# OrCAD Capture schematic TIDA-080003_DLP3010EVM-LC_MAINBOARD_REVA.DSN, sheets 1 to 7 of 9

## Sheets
1 P09: Disclaimer
2 P03: IT6801: size D
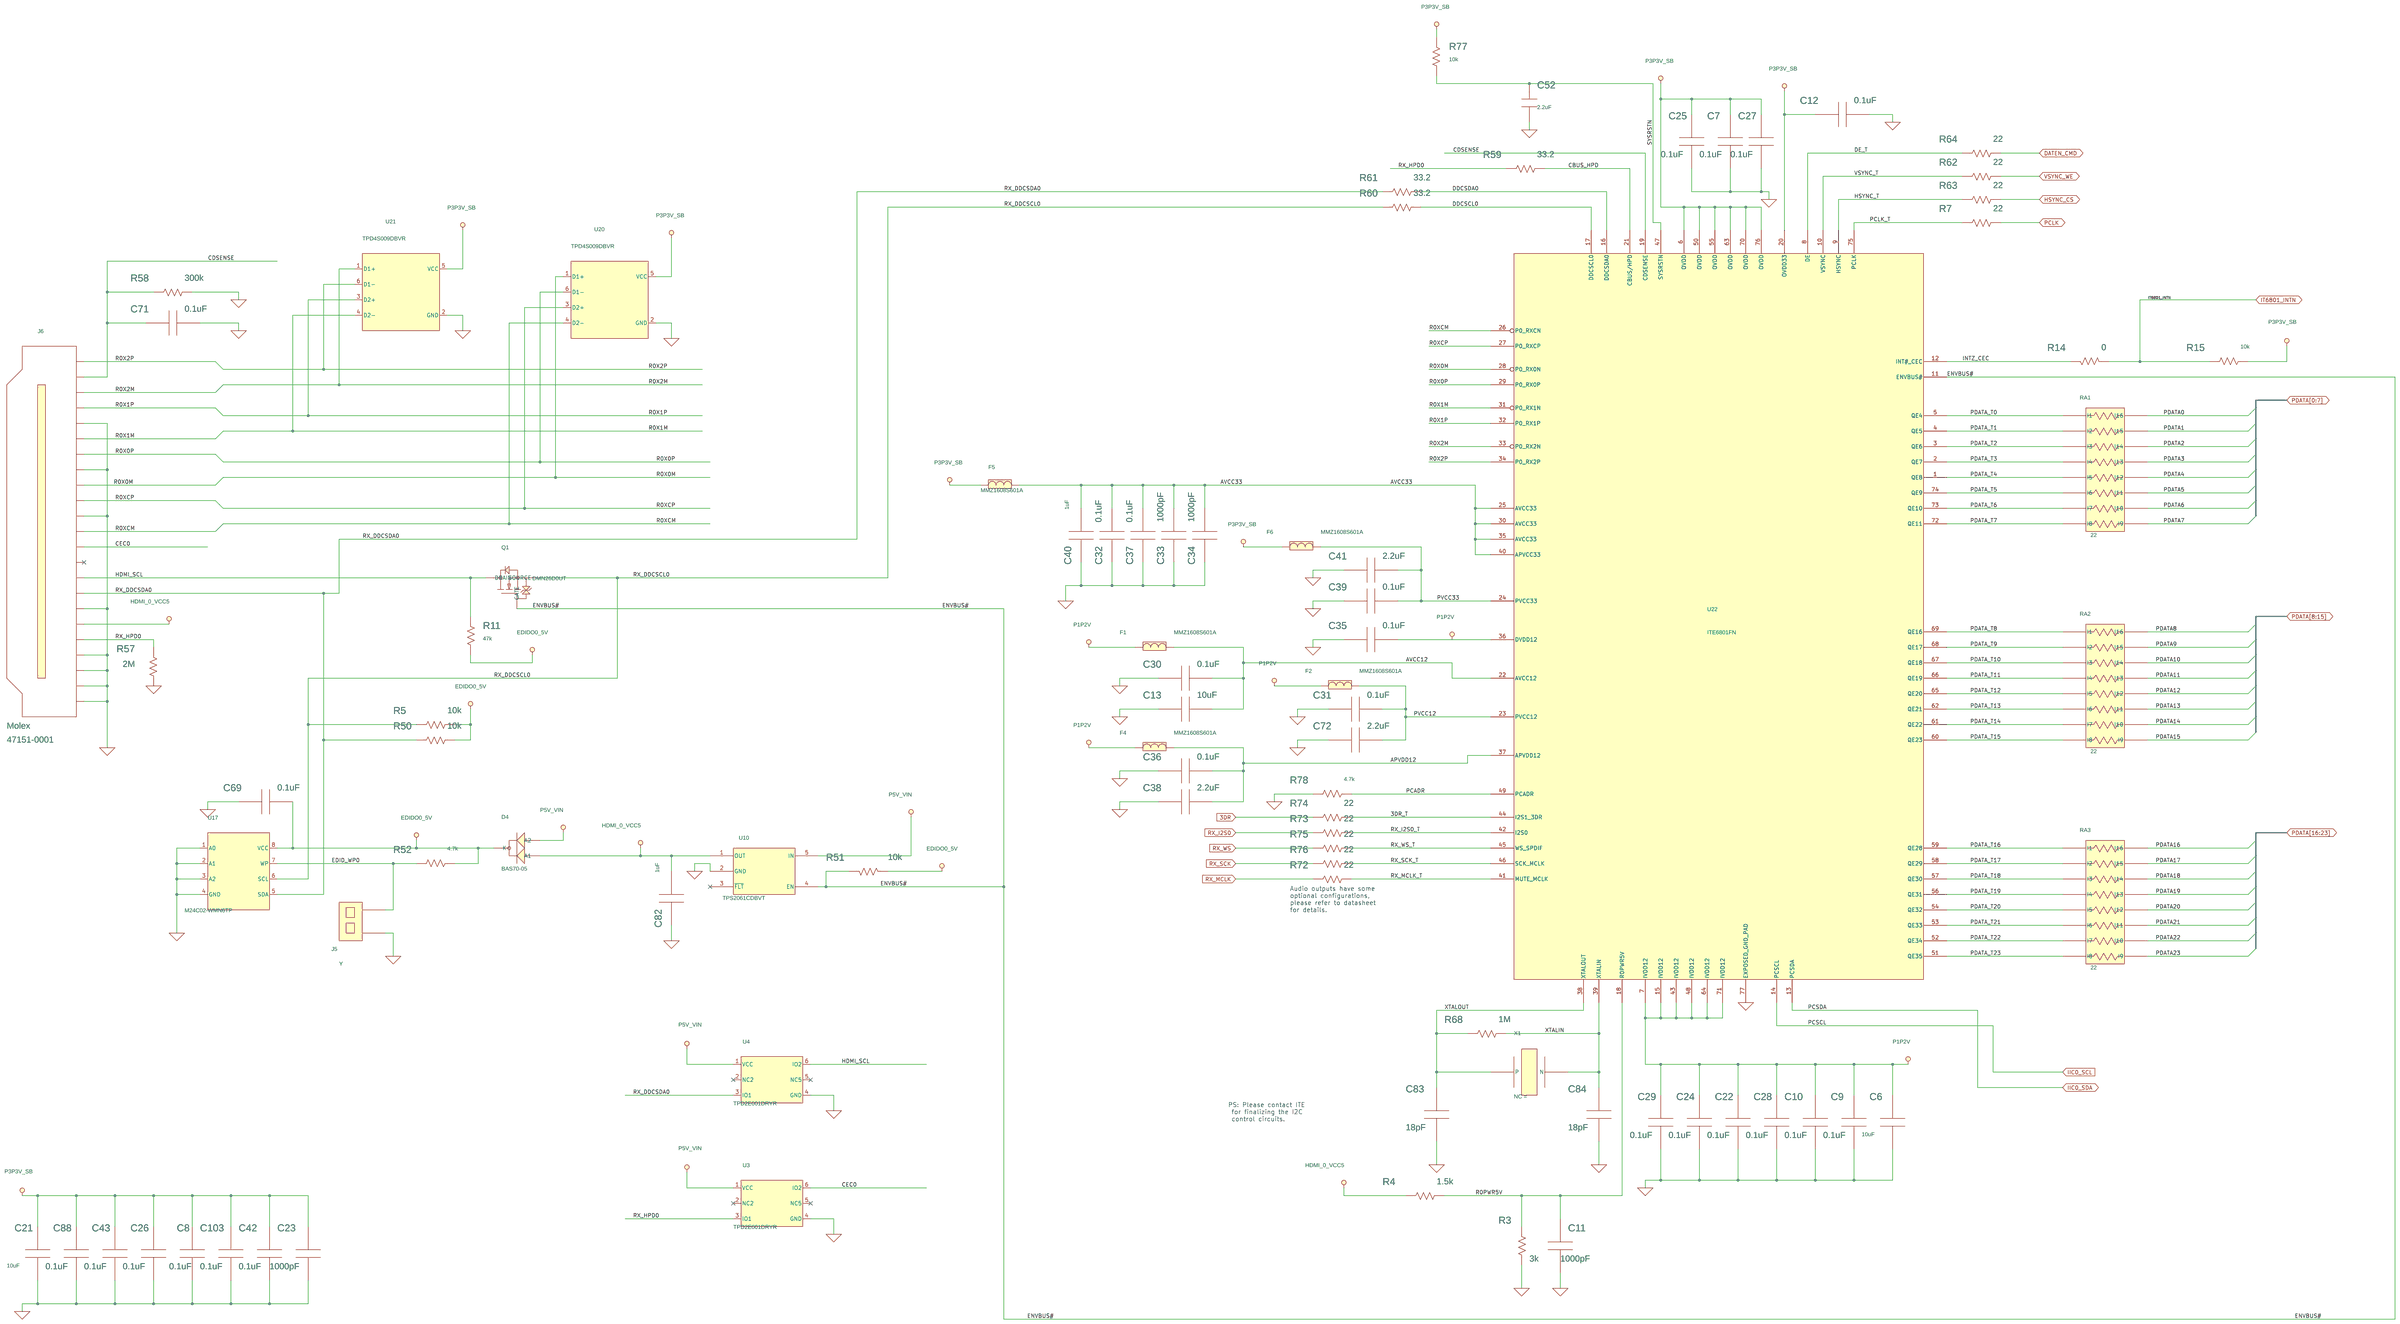
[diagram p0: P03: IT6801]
3 P01: Title: title: TIDA-080003 DLP® 3010 Light Control Main Board; rev: A; company: Texas Instruments Inc.
4 P08: Revisions
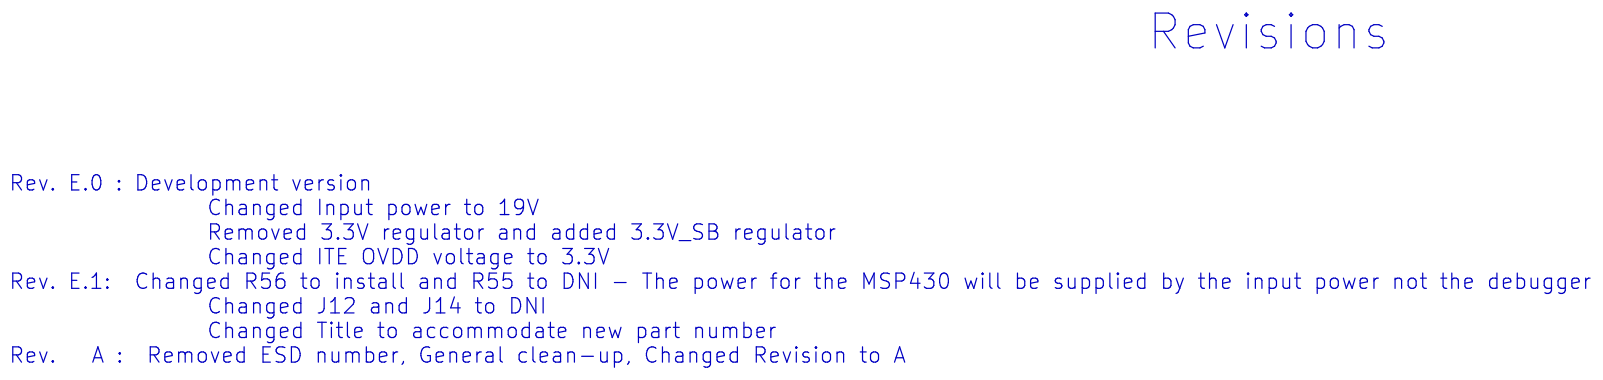
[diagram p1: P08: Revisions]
5 P02: DLP CONNECTION: size D
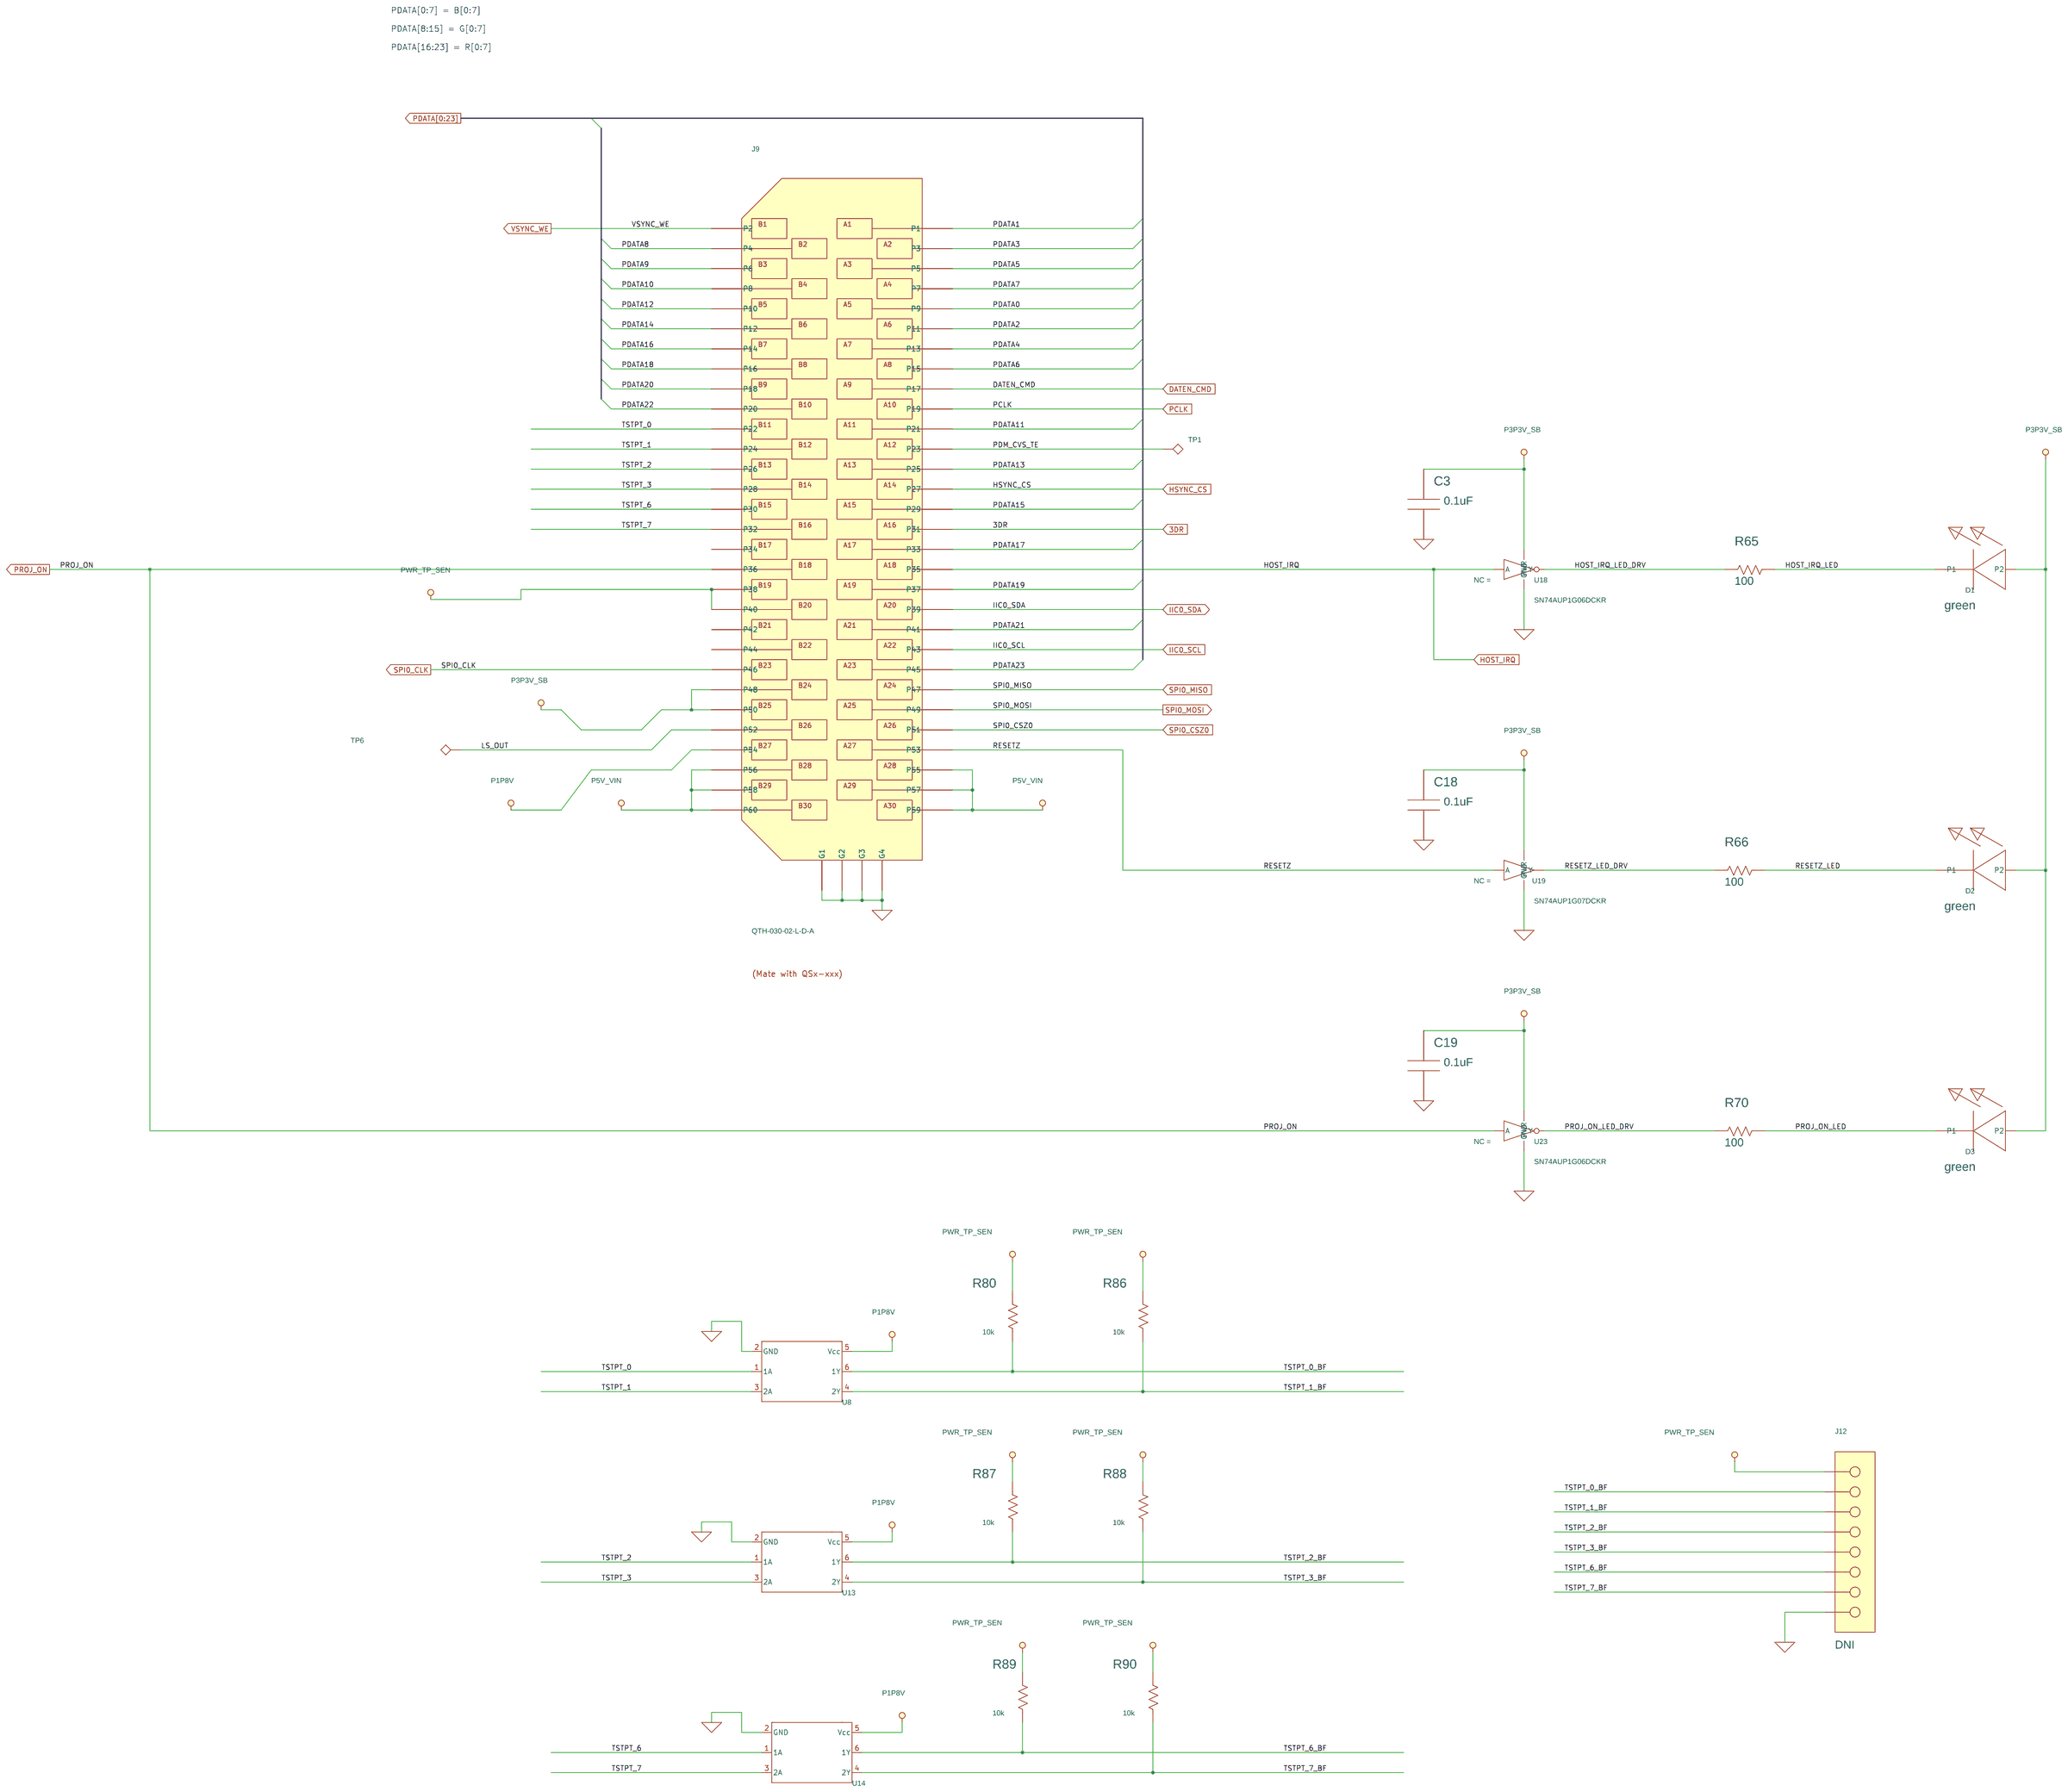
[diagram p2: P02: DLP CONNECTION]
6 P05: Audio Output: size D
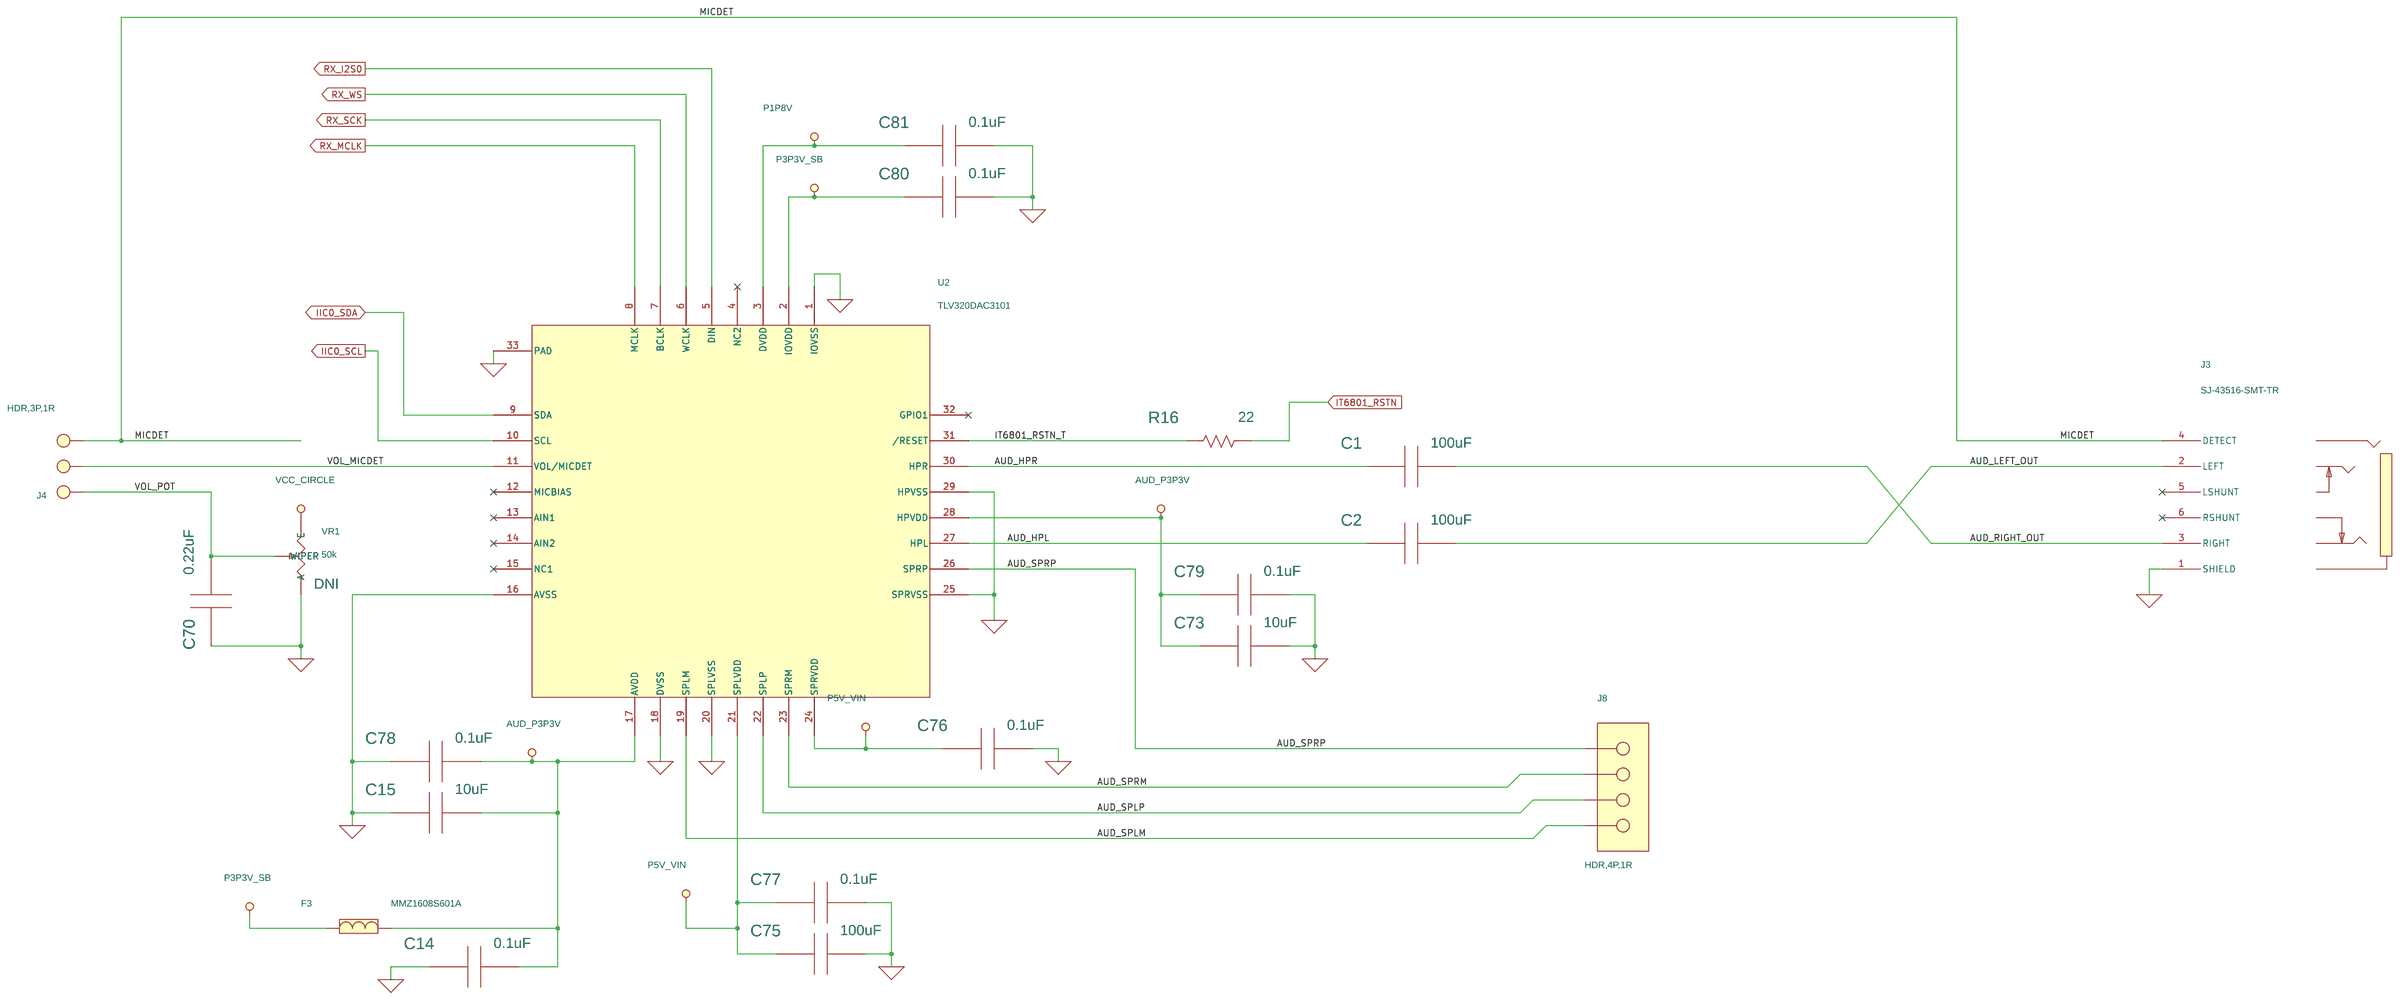
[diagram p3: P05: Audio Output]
7 P06: I2C Connections: size D
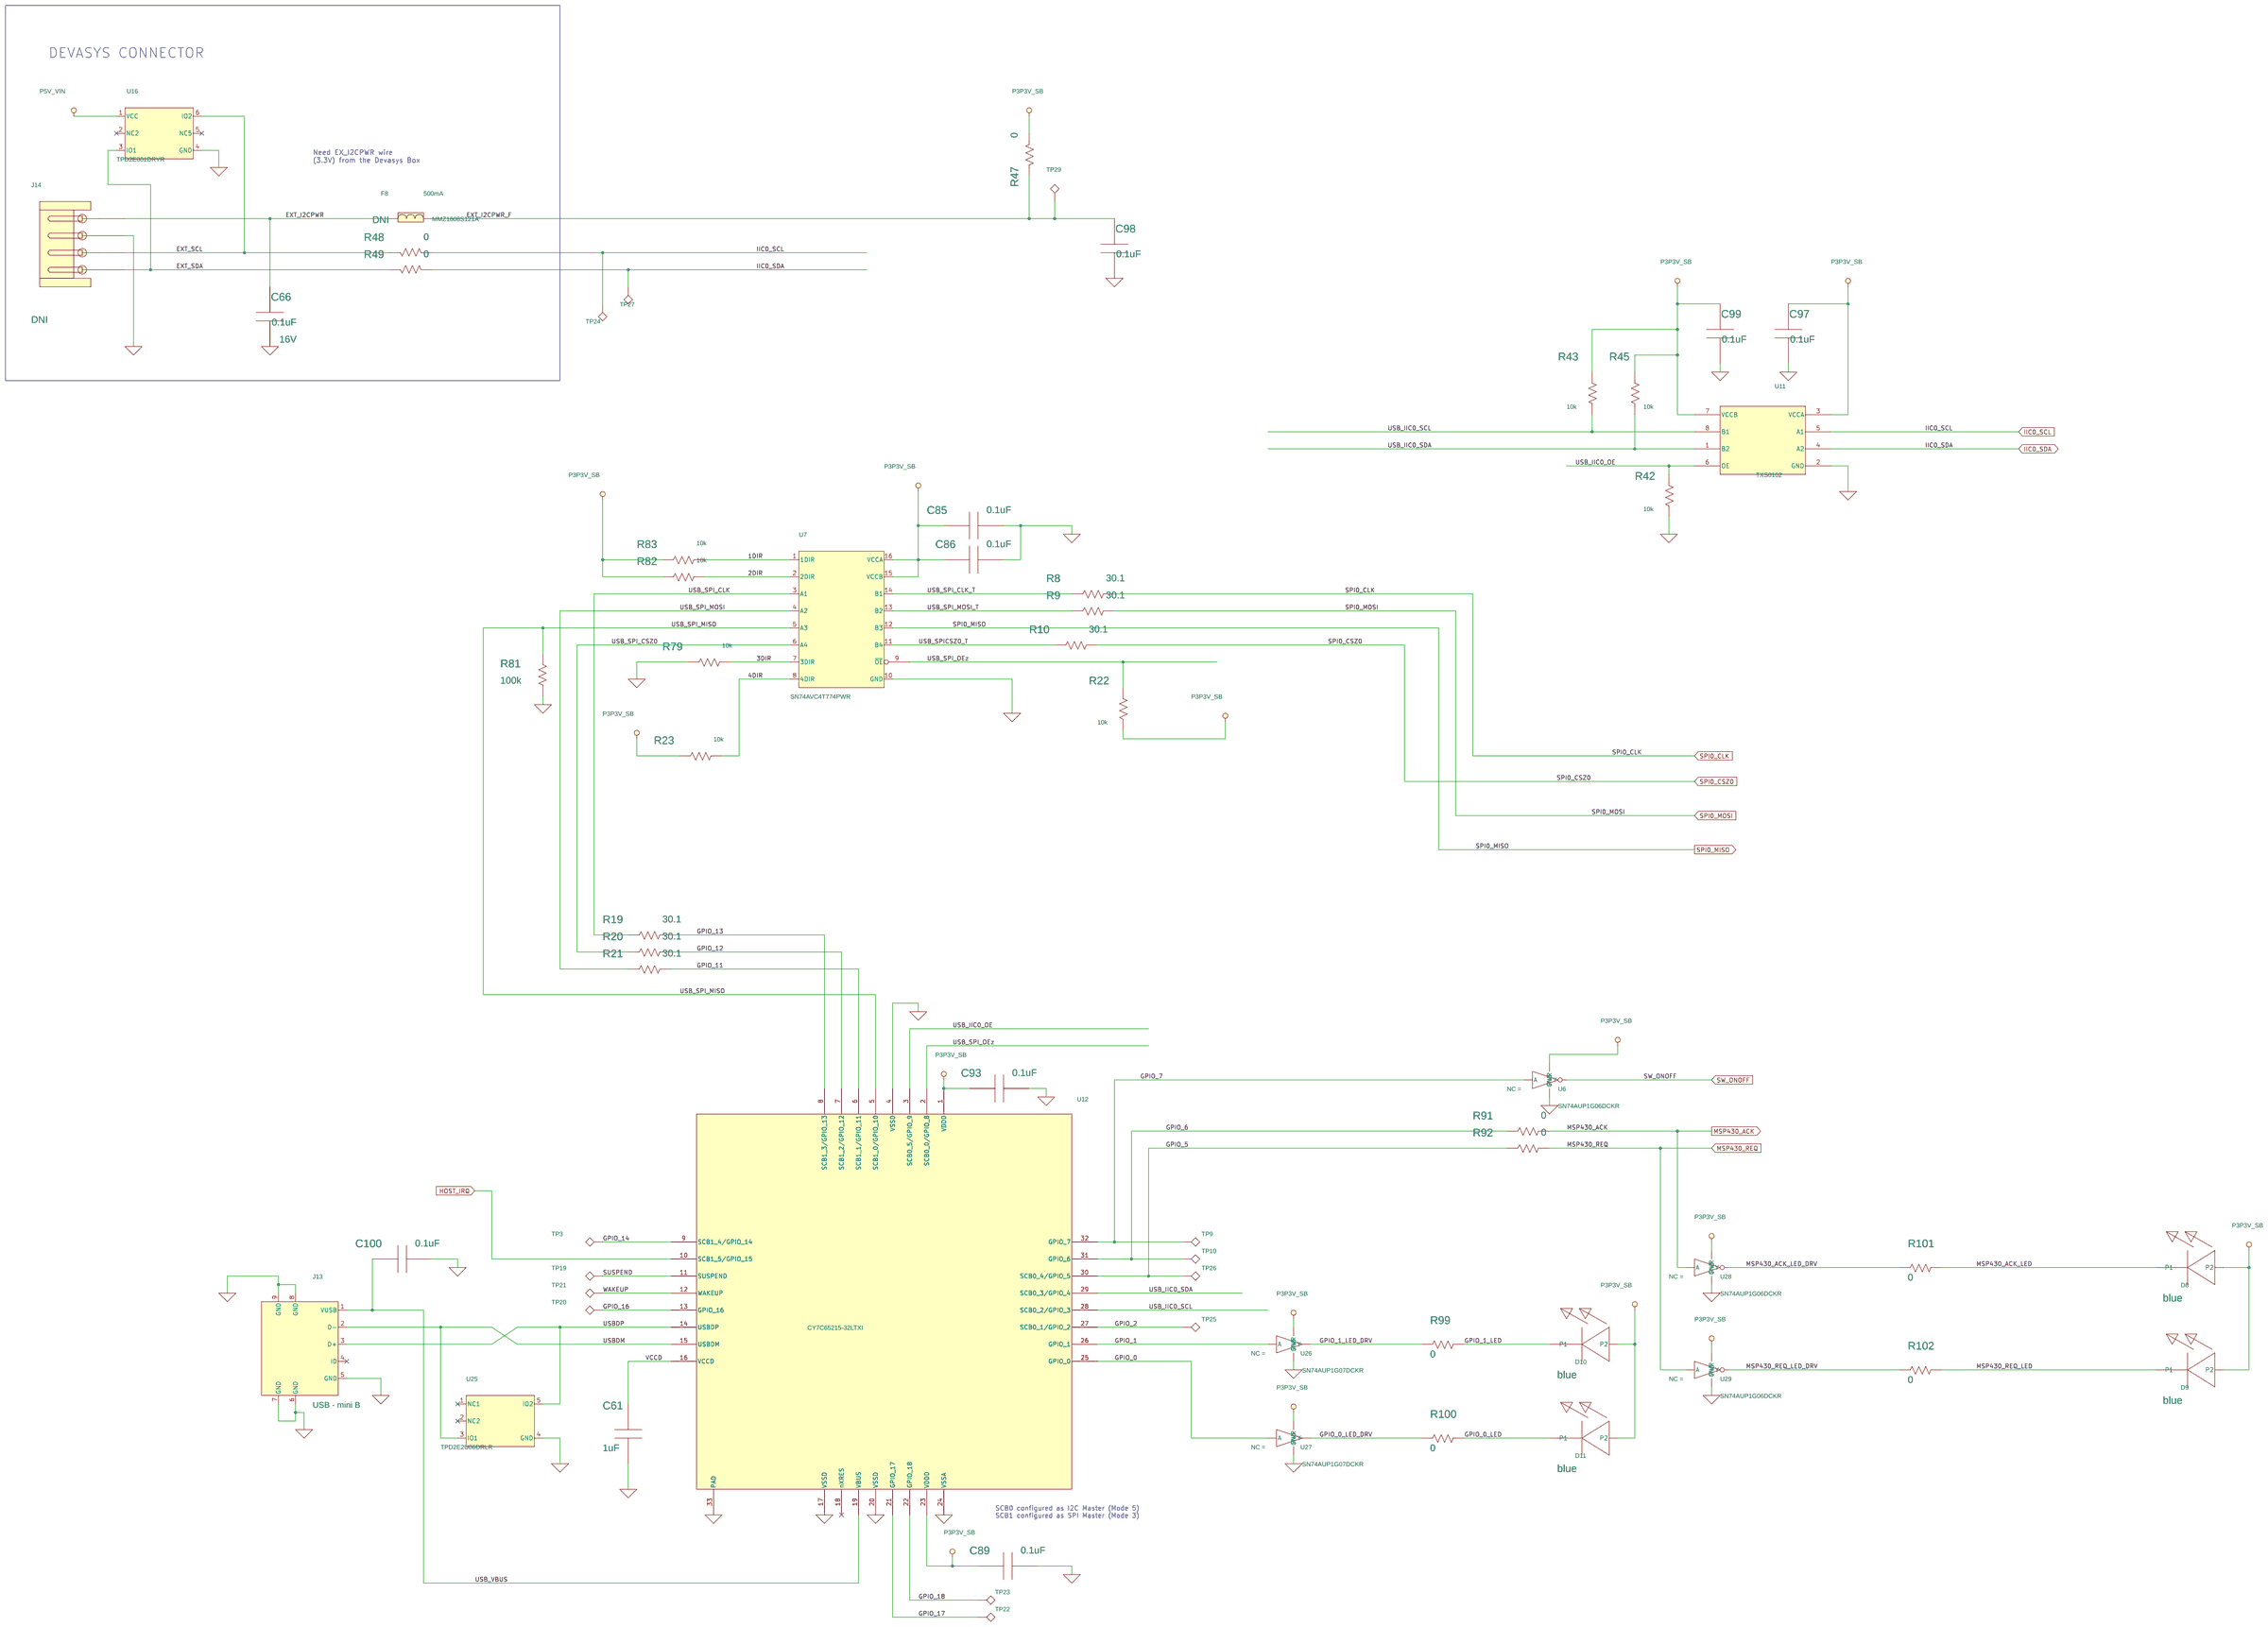
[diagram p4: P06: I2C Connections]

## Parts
sheet P02: DLP CONNECTION
C3  0.1uF  [0402_AVXA]
C18  0.1uF  [0402_AVXA]
C19  0.1uF  [0402_AVXA]
D1  green  [1206]
D2  green  [1206]
D3  green  [1206]
J9  QTH-030-02-L-D-A  [Samtec_QTH-030-xx-x-D-A]
J12  EM,HDR,8P,1R, 2.54  [HDR8x1_RA]
R65  100  [0402]
R66  100  [0402]
R70  100  [0402]
R80  10k  [0402]
R86  10k  [0402]
R87  10k  [0402]
R88  10k  [0402]
R89  10k  [0402]
R90  10k  [0402]
TP1  TP,40mil Drill,60mil Pad  [HOLE_PLATED_40mil_DRILL_60mil_PAD]
TP6  TP,40mil Drill,60mil Pad  [HOLE_PLATED_40mil_DRILL_60mil_PAD]
U8  SN74AUP2G07DCK  [U_6_DCK]
U13  SN74AUP2G07DCK  [U_6_DCK]
U14  SN74AUP2G07DCK  [U_6_DCK]
U18  SN74AUP1G07DCK  [U_5_DCK]
U19  SN74AUP1G07DCK  [U_5_DCK]
U23  SN74AUP1G07DCK  [U_5_DCK]
sheet P03: IT6801
C6  10uF  [0603]
C7  0.1uF  [0402_AVXA]
C8  0.1uF  [0402_AVXA]
C9  0.1uF  [0402_AVXA]
C10  0.1uF  [0402_AVXA]
C11  1000pF  [0402]
C12  0.1uF  [0402_AVXA]
C13  10uF  [0603]
C21  10uF  [0603]
C22  0.1uF  [0402_AVXA]
C23  1000pF  [0402]
C24  0.1uF  [0402_AVXA]
C25  0.1uF  [0402_AVXA]
C26  0.1uF  [0402_AVXA]
C27  0.1uF  [0402_AVXA]
C28  0.1uF  [0402_AVXA]
C29  0.1uF  [0402_AVXA]
C30  0.1uF  [0402_AVXA]
C31  0.1uF  [0402_AVXA]
C32  0.1uF  [0402_AVXA]
C33  1000pF  [0402]
C34  1000pF  [0402]
C35  0.1uF  [0402_AVXA]
C36  0.1uF  [0402_AVXA]
C37  0.1uF  [0402_AVXA]
C38  2.2uF  [0402]
C39  0.1uF  [0402_AVXA]
C40  1uF  [0402]
C41  2.2uF  [0402]
C42  0.1uF  [0402_AVXA]
C43  0.1uF  [0402_AVXA]
C52  2.2uF  [0603]
C69  0.1uF  [0402_AVXA]
C71  0.1uF  [0402_AVXA]
C72  2.2uF  [0402]
C82  1uF  [0402]
C83  18pF  [0402]
C84  18pF  [0402]
C88  0.1uF  [0402_AVXA]
C103  0.1uF  [0402_AVXA]
D4  BAS70-05  [SOT-23]
F1  MMZ1608S601A  [0603]
F2  MMZ1608S601A  [0603]
F4  MMZ1608S601A  [0603]
F5  MMZ1608S601A  [0603]
F6  MMZ1608S601A  [0603]
J5  0022286020  [HDR2X1_RA]
J6  HDMI  [Molex_47151-0001]
Q1  DMN26D0UT  [SOT_523]
R3  3k  [0402]
R4  1.5k  [0402]
R5  10k  [0402]
R7  22  [0402]
R11  47k  [0402]
R14  0  [0402]
R15  10k  [0402]
R50  10k  [0402]
R51  10k  [0402]
R52  4.7k  [0402]
R57  2M  [0402]
R58  300k  [0402]
R59  33.2  [0402]
R60  33.2  [0402]
R61  33.2  [0402]
R62  22  [0402]
R63  22  [0402]
R64  22  [0402]
R68  1M  [0402]
R72  22  [0402]
R73  22  [0402]
R74  22  [0402]
R75  22  [0402]
R76  22  [0402]
R77  10k  [0402]
R78  4.7k  [0402]
RA1  22  [EXB-2HV]
RA2  22  [EXB-2HV]
RA3  22  [EXB-2HV]
U3  TPD2E001DRY  [U_6_DRY]
U4  TPD2E001DRY  [U_6_DRY]
U10  TPS2061CDBVT  [SOT_23_5_DBV_R-PDSO-G5]
U17  M24C02-WMN6TP  [SOIC-8_3p90mm_wide]
U20  TPD4S009DBVR  [SOT23-6_DBV_R-PDSO-G6]
U21  TPD4S009DBVR  [SOT23-6_DBV_R-PDSO-G6]
U22  ITE6801FN  [ITE6801_76pin_QFN]
X1  27.000MHz  [Abracon_ABM8]
sheet P05: Audio Output
C1  100uF  [1210]
C2  100uF  [1210]
C14  0.1uF  [0402_AVXA]
C15  10uF  [0603]
C70  0.22uF  [0402]
C73  10uF  [0603]
C75  100uF  [1210]
C76  0.1uF  [0402_AVXA]
C77  0.1uF  [0402_AVXA]
C78  0.1uF  [0402_AVXA]
C79  0.1uF  [0402_AVXA]
C80  0.1uF  [0402_AVXA]
C81  0.1uF  [0402_AVXA]
F3  MMZ1608S601A  [0603]
J3  SJ-43516-SMT-TR  [CUI_SJ-43516-SMT]
J4  HDR,3P,1R  [TSW-103-07-G-S]
J8  HDR,4P,1R  [HDR4P_1R]
R16  22  [0402]
U2  TLV320DAC3101  [QFN-32_RHB_S-PVQFN-N32]
VR1  50k  [BOURNS_3352H-1-503LF]
sheet P06: I2C Connections
C61  1uF  [0402]
C66  0.1uF  [0402_AVXA]
C85  0.1uF  [0402_AVXA]
C86  0.1uF  [0402_AVXA]
C89  0.1uF  [0402_AVXA]
C93  0.1uF  [0402_AVXA]
C97  0.1uF  [0402_AVXA]
C98  0.1uF  [0402_AVXA]
C99  0.1uF  [0402_AVXA]
C100  0.1uF  [0402_AVXA]
D8  blue  [1206]
D9  blue  [1206]
D10  blue  [1206]
D11  blue  [1206]
F8  MMZ1608S121A  [0603]
J13  USB - mini B USB 2.0  [conn5_usb_b_mini_MOLEX]
J14  S4B-EH(LF)(SN)  [CONN4-S4B-EH_JST]
R8  30.1  [0402]
R9  30.1  [0402]
R10  30.1  [0402]
R19  30.1  [0402]
R20  30.1  [0402]
R21  30.1  [0402]
R22  10k  [0402]
R23  10k  [0402]
R42  10k  [0402]
R43  10k  [0402]
R45  10k  [0402]
R47  0  [0402]
R48  0  [0402]
R49  0  [0402]
R79  10k  [0402]
R81  100k  [0402]
R82  10k  [0402]
R83  10k  [0402]
R91  0  [0402]
R92  0  [0402]
R99  0  [0402]
R100  0  [0402]
R101  0  [0402]
R102  0  [0402]
TP3  TP40  [TP40]
TP9  TP40  [TP40]
TP10  TP40  [TP40]
TP19  TP40  [TP40]
TP20  TP40  [TP40]
TP21  TP40  [TP40]
TP22  TP40  [TP40]
TP23  TP40  [TP40]
TP24  TP40  [TP40]
TP25  TP40  [TP40]
TP26  TP40  [TP40]
TP27  TP40  [TP40]
TP29  TP40  [TP40]
U6  SN74AUP1G07DCK  [U_5_DCK]
U7  SN74AVC4T774PWR  [TSSOP16_PW]
U11  TXS0102  [VSSOP-8_DCU]
U12  CY7C65215-32LTXI  [CY7C65215_32pin_QFN]
U16  TPD2E001DRY  [U_6_DRY]
U25  TPD2E2U06DRL  [SOT-5_DRL_R-PDSO-N5]
U26  SN74AUP1G07DCK  [U_5_DCK]
U27  SN74AUP1G07DCK  [U_5_DCK]
U28  SN74AUP1G07DCK  [U_5_DCK]
U29  SN74AUP1G07DCK  [U_5_DCK]

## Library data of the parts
C3 C7-C10 C12 C14 C18 C19 C22 C24-C32 C35-C37 C39 C42 C43 C66 C69 C71 C76-C81 C85 C86 C88 C89 C93 C97-C100 C103 = PAS,CAP,NP,large: DigiKey: 445-4952-1-ND; DigiReel: 445-4952-6-ND; Family: passive; Index PN: 681; Lead Style: SMT; MFG: TDK; Material: x7r; P/D_NUM: C1005X7R1C104K050BC; Part Number: C1005X7R1C104K050BC; Part Specific: CAP CER .1UF 16V X7R 0402; TOLERANCE: 10%; Type: capacitor; VENDOR: TDK; VPC: 16V
D1-D3 = PAS,DIODE,LED,large: DigiKey: 67-1357-1-ND; DigiReel: 67-1357-6-ND; Family: passive; Index PN: 31; Install: Y; Lead Style: SMT; MFG: Lumex; P/D_NUM: SML-LX1206GC-TR; Part Number: SML-LX1206GC-TR; Part Specific: LED 565NM WTR CLR GREEN 1206 SMD; Type: diode,led; VENDOR: Lumex
J9 = EM,CONN,60P,QTx: DigiKey: SAM8186-ND; Family: electro/mechanical; Index PN: 1197; Lead Style: SMT; MFG: Samsung; Part Specific: CONN HEADER HS .5MM 60POS DL AU (stacking ht 8mm); Pin Cnt: 60; Pin Spacing: 0.5mm; Row Cnt: 2; Type: connector; Vendor: Samsung
J12 = EM,HDR,8P,1R,2X_1: DigiKey: S1111EC-08-ND; Install: DNI; P/D_NUM: PRPC008SBAN-M71RC; Part Number: PRPC008SBAN-M71RC; Part Specific: CONN HEADER .100" SNGL R/A 8POS; Type: Header Male Breakaway; Vendor: Sullins
R65 R66 R70 = PAS,R,large: DigiKey: MCS0402-100-CFCT-ND; DigiReel: MCS0402-100-CFDKR-ND; Family: passive; Lead Style: SMT; MFG: Vishay Beyschlag; Material: chip; P/D_NUM: MCS04020C1000FE000; Part Number: MCS04020C1000FE000; Part Specific: RES 100 OHM 1/10W 1% 0402 SMD; Power: 1/10W; TOLERANCE: 1%; Type: resistor; VENDOR: Vishay Beyschlag; VPC: 1/10W
R15 R23 R43 R45 R77 R79 R80 R82 R83 R86-R90 = PAS,R,large: DigiKey: P10.0KLCT-ND; DigiReel: P10.0KLDKR-ND; Family: passive; Index PN: 680; Lead Style: SMT; MFG: Panasonic; Material: chip; P/D_NUM: ERJ-2RKF1002X; Part Number: ERJ-2RKF1002X; Part Specific: RES SMD 10K OHM 1% 1/10W 0402; Power: 1/16W; TOLERANCE: 1%; Type: resistor; VENDOR: Panasonic; VPC: 1/16W
TP1 TP6 = BF,HOLE,PLATED,TESTPIN: DigiKey: ---; DigiReel: ---; Family: board feature; Index PN: 377; Install: DNI; Lead Style: TH; MFG: -- NOT A PART --; Type: hole,plated; Vendor: -- NOT A PART --
U8 U13 U14 = TMP_155743: DigiKey: 296-27357-1-ND; DigiReel: 296-27357-6-ND; Family: logic; Part Specific: IC BUFF/DRIVER DUAL LP SC70-6; Type: buffer
U6 U18 U23 U28 U29 = LOG,INV,OPENDRN,SN74AUP1G06DCK: DigiKey: 296-17562-1-ND; DigiReel: 296-17562-6-ND; Family: logic; Index PN: 1026; Lead Style: SMT; MFG: Texas Instruments; P/D_NUM: SN74AUP1G06DCKR; Part Number: SN74AUP1G06DCKR; Part Specific: IC INVERTER SINGLE 1INPUT SC705, open drain; Type: buffer
U19 U26 U27 = LOG,BUF,OPENDRN,SN74AUP1G07DCK: DigiKey: 296-18256-1-ND; DigiReel: 296-18256-6-ND; Family: logic; Index PN: 1027; Install: Y; Lead Style: SMT; MFG: Texas Instruments; P/D_NUM: SN74AUP1G07DCKR; Part Number: SN74AUP1G07DCKR; Part Specific: IC BUFF/DVR LOW PWR N-INV SC705, open drain; Type: buffer
C6 C13 C15 C21 C73 = PAS,CAP,NP,large: DigiKey: 445-4112-1-ND; DigiReel: 445-4112-6-ND; Family: passive; Index PN: 906; Lead Style: SMT; MFG: TDK; Material: x5r; P/D_NUM: C1608X5R0J106M080AB; Part Number: C1608X5R0J106M080AB; Part Specific: CAP CERAMIC 10UF 6.3V X5R 0603; TOLERANCE: 20%; Type: capacitor; VENDOR: TDK; VPC: 6.3V
C11 C23 C33 C34 = PAS,CAP,NP,large: DigiKey: 490-6325-1-ND; DigiReel: 490-6325-6-ND; Family: passive; Lead Style: SMT; MFG: Murata; Material: x7r; P/D_NUM: GRM155R71C102KA01D; Part Number: GRM155R71C102KA01D; Part Specific: CAP CERAMIC .001UF 16V X7R 0402; TOLERANCE: 10%; Type: capacitor; VENDOR: Murata; VPC: 16V
C38 C41 C72 = PAS,CAP,NP,large: DigiKey: 445-4999-1-ND; DigiReel: 445-4999-6-ND; Family: passive; Index PN: 915; Lead Style: SMT; MFG: TDK; Material: x5r; P/D_NUM: C1005X5R0J225M; Part Number: C1005X5R0J225M; Part Specific: CAP CER 2.2UF 6.3V X5R 0402; TOLERANCE: 10%; Type: capacitor; VENDOR: TDK; VPC: 6.3V
C40 C61 C82 = PAS,CAP,NP,large: DigiKey: 587-3245-1-ND; DigiReel: 587-3245-6-ND; Family: passive; Lead Style: SMT; MFG: Taiyo Yuden; Material: x5r; P/D_NUM: TMK105BJ105MV-F; Part Number: TMK105BJ105MV-F; Part Specific: CAP CER 1.0UF 25V X5R 0402; TOLERANCE: 20%; Type: capacitor; VENDOR: Taiyo Yuden; VPC: 25V
C52 = CER_2.2UF_25V_10%_X5R_0603: DigiKey: 587-2909-1-ND; DigiReel: 587-2909-6-ND; Install: Y; P/D_NUM: TMK107ABJ225KA-T; Part Specific: 2.2µF 25V Ceramic Capacitor X5R 0603; Type: Capacitor; VPC: 25V; Vendor: Taiyo Yuden
C83 C84 = PAS,CAP,NP,large: DigiKey: 445-1238-1-ND; DigiReel: 445-1238-6-ND; Family: passive; Index PN: 960; Lead Style: SMT; MFG: TDK; Material: npo; P/D_NUM: C1005C0G1H180J; Part Number: C1005C0G1H180J; Part Specific: CAP CER 18PF 50V C0G 5% 0402; Type: capacitor; VENDOR: TDK; VPC: 50V
D4 = PAS,DIODE,BAV70_SOT_23_3: DigiKey: BAS70-05FDICT-ND; DigiReel: BAS70-05FDIDKR-ND; Family: passive; Index PN: 1238; MFG: Diodes Incorporated; P/D_NUM: BAS70-05-7-F; Part Number: BAS70-05-7-F; Part Specific: DIODE SCHOTTKY 70V 70MA SOT23; Type: diode,schottky; Vendor: Diodes Incorporated
F1-F6 = PAS,FERRITE_BEAD,3: DigiKey: 445-1549-1-ND; DigiReel: 445-1549-6-ND; Family: passive; Index PN: 1135; Lead Style: SMT; MFG: TDK; Part Specific: FERRITE CHIP 600 OHM 500MA 0603; Type: ferrite bead; Vendor: TDK
J5 = 2POS_SMT_HEADER_2_0.54MM: Header Breakaway, Right Angle 0.100" 2POS TIN; DigiKey: WM13454-ND; Digikey Part Number: WM13454-ND; Install: Y; MFG: Molex; Part Specific: 2 Positions Header, Right Angle; Type: 2 Pos. Header; Vendor: Harwin
J6 = EM,CONN,HDMI,1R: DigiKey: WM19086CT-ND; DigiReel: WM19086DKR-ND; Index PN: 1136; Lead Style: SMT; MFG: Molex; P/D_NUM: 47151-0001; Part Number: 47151-0001; Part Specific: CONN RCPT 19POS HDMI RT ANG SMD; Vendor: Molex
Q1 = ANA,MOSFET,N-CH,E,DMN26U,SOT-23: DigiKey: DMN26D0UT-7DICT-ND; DigiReel: DMN26D0UT-7DIDKR-ND; Family: analog; Index PN: 1236; Lead Style: SMT; MFG: Diodes Incorporated; Part Specific: MOSFET N-CH 20V 230MA SOT523; Type: mosfet; VPC: 60V; Vendor: Diodes Incorporated
R3 = PAS,R,large: DigiKey: P3.00KLCT-ND; DigiReel: P3.00KLDKR-ND; Family: passive; Index PN: 1230; Lead Style: SMT; MFG: Panasonic; P/D_NUM: ERJ-2RKF3001X; Part Number: ERJ-2RKF3001X; Part Specific: RES 3K OHM 1/10W 1% 0402 SMD; TOLERANCE: 1%; Type: resistor; VENDOR: Panasonic; VPC: 1/10W
R4 = PAS,R,large: DigiKey: P1.50KLCT-ND; DigiReel: P1.50KLDKR-ND; Family: passive; Index PN: 1117; Lead Style: SMT; MFG: Panasonic; Material: chip; P/D_NUM: ERJ-2RKF1501X; Part Number: ERJ-2RKF1501X; Part Specific: RES 1.50K OHM 1/10W 1% 0402 SMD; TOLERANCE: 1%; Type: resistor; VENDOR: Panasonic; VPC: 1/10W
R5 R22 R42 R50 R51 = PAS,R,large: DigiKey: P10.0KLCT-ND; DigiReel: P10.0KLDKR-ND; Family: passive; Index PN: 680; Install: Y; Lead Style: SMT; MFG: Panasonic; Material: chip; P/D_NUM: ERJ-2RKF1002X; Part Number: ERJ-2RKF1002X; Part Specific: RES SMD 10K OHM 1% 1/10W 0402; Power: 1/16W; TOLERANCE: 1%; Type: resistor; VPC: 1/16W; Vendor: Panasonic
R7 R16 R62-R64 R72-R76 = PAS,R,large: DigiKey: 311-22.0LRCT-ND; DigiReel: 311-22.0LRDKR-ND; Family: passive; Index PN: 1215; Lead Style: SMT; MFG: Yageo; Material: chip; P/D_NUM: RC0402FR-0722RL; Part Number: RC0402FR-0722RL; Part Specific: RES 22.0 OHM 1/16W 1% 0402 SMD; TOLERANCE: 1%; Type: resistor; VENDOR: Yageo; VPC: 1/16W
R11 = PAS,R,large: DigiKey: P47.0KLCT-ND; DigiReel: P47.0KLDKR-ND; Family: passive; Index PN: 1030; Lead Style: SMT; MFG: Panasonic; Material: chip; P/D_NUM: ERJ-2RKF4702X; Part Number: ERJ-2RKF4702X; Part Specific: RES 47.0K OHM 1/10W 1% 0402 SMD; TOLERANCE: 1%; Type: resistor; VENDOR: Panasonic; VPC: 1/16W
R14 R48 R49 R91 R92 = PAS,R,large: DigiKey: P0.0JCT-ND; DigiReel: P0.0JDKR-ND; Family: passive; Index PN: 687; Lead Style: SMT; MFG: Panasonic; Material: chip; P/D_NUM: ERJ-2GE0R00X; Part Number: ERJ-2GE0R00X; Part Specific: RES 0.0 OHM 1/16W 0402 SMD; Power: 1/16W; Type: resistor; VPC: 1/16W; Vendor: Panasonic
R52 R78 = PAS,R,large: DigiKey: P4.70KLCT-ND; DigiReel: P4.70KLDKR-ND; Family: passive; Index PN: 1219; Lead Style: SMT; MFG: Panasonic; P/D_NUM: ERJ-2RKF4701X; Part Number: ERJ-2RKF4701X; Part Specific: RES 4.7K OHM 1/10W 1% 0402 SMD; TOLERANCE: 1%; Type: resistor; VENDOR: Panasonic; VPC: 1/16W
R57 = PAS,R,large: DigiKey: P2.0MJCT-ND; DigiReel: P2.0MJDKR-ND; Family: passive; Index PN: 1237; Install: Y; Lead Style: SMT; MFG: Panasonic; P/D_NUM: ERJ-2GEJ205X; Part Number: ERJ-2GEJ205X; Part Specific: RES 2M OHM 1/10W 5% 0402 SMD; TOLERANCE: 5%; Type: resistor; VPC: 1/10W; Vendor: Panasonic
R58 = PAS,R,large: DigiKey: 311-300KLRCT-ND; DigiReel: 311-300KLRDKR-ND; Family: passive; Index PN: 1181; Lead Style: SMT; MFG: Yageo; P/D_NUM: RC0402FR-07300KL; Part Number: RC0402FR-07300KL; Part Specific: RES 300K OHM 1/16W 1% 0402 SMD; TOLERANCE: 1%; Type: resistor; VENDOR: Yageo; VPC: 1/16W
R59-R61 = PAS,R,large: DigiKey: P33.2LCT-ND; DigiReel: P33.2LDKR-ND; Family: passive; Index PN: 725; MFG: Panasonic; Material: chip; P/D_NUM: ERJ-2RKF33R2X; Part Number: ERJ-2RKF33R2X; Part Specific: RES 33.2 OHM 1/16W 1% 0402 SMD; Power: 1/16W; TOLERANCE: 1%; Type: resistor; VENDOR: Panasonic; VPC: 1/16W
R68 = PAS,R,large: DigiKey: P1.00MLCT-ND; DigiReel: P1.00MLDKR-ND; Family: passive; Index PN: 1229; Lead Style: SMT; MFG: Panasonic; P/D_NUM: ERJ-2RKF1004X; Part Number: ERJ-2RKF1004X; Part Specific: RES 1M OHM 1/10W 1% 0402 SMD; TOLERANCE: 1%; Type: resistor; VENDOR: Panasonic; VPC: 1/10W
RA1-RA3 = PAS,R,ARRAY,8,SM: DigiKey: Y1220CT-ND; DigiReel: Y1220DKR-ND; Index PN: 1214; Lead Style: SMT; MFG: Panasonic; Material: chip; P/D_NUM: EXB-2HV220JV; Part Number: EXB-2HV220JV; Part Specific: RES ARRAY 22 OHM 8 RES 1506; Tolerance: 5%; Type: resistor; VPC: 31mW; Vendor: Panasonic
U3 U4 U16 = TPD2E001DRY: DigiKey: 296-21884-1-ND; DigiReel: 296-21884-6-ND; Family: passive; Index PN: 1029; Install: Y; Lead Style: SMT; MFG: Texas Instruments; P/D_NUM: TPD2E001DRYR; Part Number: TPD2E001DRYR; Part Specific: IC ESD-PROT ARRAY 2CH 6-SON; Type: diode,tvs
U10 = PWR,SW,TPS2601CDBV: DigiKey: 296-35522-1-ND; DigiReel: 296-35522-6-ND; Family: power; Index PN: 1224; Lead Style: SMT; MFG: Texas Instruments; Part Specific: IC PWR DIST SWITCH SGL SOT23-5; Type: switch; Vendor: Texas Instruments
U17 = MEM,EEPROM,24LCxx,2x: DigiKey: 497-8552-1-ND; DigiReel: 497-8552-6-ND; Family: memory; Index PN: 1131; Lead Style: SMT; MFG: Stmicroelectronics; Part Specific: IC EEPROM 2KBIT 400KHZ 8SOIC; Type: eeprom; Vendor: Stmicroelectronics
U20 U21 = PAS,DIODE,ARRAY,TVS,SOT23-6: DigiKey: 296-23749-1-ND; DigiReel: 296-23749-6-ND; Family: passive; Index PN: 1132; Install: Y; Lead Style: SMT; MFG: Texas Instruments; Part Specific: IC 4CH ESD SOLUTION SOT23-6; Type: diode,tvs; Vendor: Texas Instruments
U22 = INF,VIDEO,IT6801: DigiKey: ---; DigiReel: ---; Family: interface; Index PN: 1218; Lead Style: SMT; MFG: ITE Tech Inc; P/D_NUM: IT6801FN; Part Number: IT6801FN; Part Specific: HDMI Rcvr; Type: video; Vendor: ITE Tech Inc; Vendor P/N: IT6801FN
X1 = PAS,CRYSTAL,NX3225GA: DigiKey: 535-9141-1-ND; DigiReel: 535-9141-6-ND; Family: passive; Index PN: 1231; Lead Style: SMT; MFG: Abracon; P/D_NUM: ABM8-27.000MHZ-B2-T; Part Number: ABM8-27.000MHZ-B2-T; Part Specific: CRYSTAL 27MHZ 18PF SMD; Type: crystal; Vendor: Abracon
C1 C2 C75 = PAS,CAP,NP,large: DigiKey: 587-3152-1-ND; DigiReel: 587-3152-2-ND; Family: passive; Index PN: 1227; Lead Style: SMT; MFG: Taiyo Yuden; Material: x5r; P/D_NUM: EMK325ABJ107MM-T; Part Number: EMK325ABJ107MM-T; Part Specific: CAP CER 100UF 16V 20% X5R 1210; TOLERANCE: 20%; Type: capacitor; VENDOR: Taiyo Yuden; VPC: 16V
C70 = PAS,CAP,NP,large: DigiKey: 445-5944-1-ND; DigiReel: 445-5944-6-ND; Family: passive; Index PN: 1173; Lead Style: SMT; MFG: TDK; Material: x5r; P/D_NUM: C1005X5R1E224K050BC; Part Number: C1005X5R1E224K050BC; Part Specific: CAP CER 0.22UF 25V 10% X5R 0402; TOLERANCE: 10%; Type: capacitor; VENDOR: TDK; VPC: 25V
J3 = EM,CONN,PHONOJACK,4C,V1,pinout2: DigiKey: CP-43516SJCT-ND; Family: electro/mechanical; Index PN: 1232; Lead Style: SMT; MFG: CUI Stack; Part Specific: CONN AUDIO JACK 3.5MM 4COND SMD; Type: connector; Vendor: CUI Stack
J4 = EM,JMP,3P,1R: DigiKey: SAM1029-03-ND; DigiReel: ---; Index PN: 20; Lead Style: TH; MFG: Samtec; Part Specific: PLUG; Pin Cnt: 3; Pin Spacing: 100mil; Row Cnt: 1; Type: header; Vendor: Samtec
J8 = EM,HDR,4P,1R,2x: DigiKey: SAM1053-04-ND; Family: electro/mechanical; Index PN: 819; Lead Style: TH; MFG: Samtec; P/D_NUM: TSW-104-14-G-S; Part Number: TSW-104-14-G-S; Part Specific: PLUG; Pin Cnt: 4; Pin Spacing: 100mil; Row Cnt: 1; Type: header; Vendor: Samtec
U2 = INF,DAC,TLV320DAC3101: DigiKey: 296-25780-1-ND; DigiReel: 296-25780-6-ND; Family: interface; Index PN: 1225; Lead Style: SMT; MFG: Texas Instruments; P/D_NUM: TLV320DAC3101IRHBR; Part Number: TLV320DAC3101IRHBR; Part Specific: IC STEREO AUD DAC CLASS-D LP 32QFN; Type: dac; Vendor: Texas Instruments
VR1 = PAS,POT: DigiKey: 3352H-503LF-ND; DigiReel: ---; Family: passive; Index PN: 1228; Install: DNI; Lead Style: TH; MFG: Bourns; P/D_NUM: 3352H-1-503LF; Part Number: 3352H-1-503LF; Part Specific: POT 50K OHM THUMBWHEEL CERM ST; Type: potentiometer; Vendor: Bourns
D8-D11 = PAS,DIODE,LED,large: DigiKey: 67-1701-1-ND; DigiReel: 67-1701-6-ND; Family: passive; Index PN: 1250; Install: Y; Lead Style: SMT; MFG: Lumex; P/D_NUM: SML-LX1206USBC-TR; Part Number: SML-LX1206USBC-TR; Part Specific: LED INGAN/SIC U-BLUE CLR 1206SMD; Type: diode,led; VENDOR: Lumex
F8 = PAS,FERRITE_BEAD,3: DigiKey: 445-2173-1-ND; DigiReel: 445-2173-6-ND; Family: passive; Index PN: 1141; Install: DNI; Lead Style: SMT; MFG: TDK; Part Specific: FERRITE CHIP 120 OHM 500MA 06; Type: ferrite bead; VENDOR: TDK; VPC: 500mA
J13 = CON5_1: DigiKey: WM5461CT-ND; DigiReel: WM5461DKR-ND; Family: electro/mechanical; Install: Y; Lead Style: SMT; MFG: Molex; P/D_NUM: 0675031020; Part Number: 0675031020; Part Specific: CONN RECEPT MINI-USB R/A 5POS SMD; Pin Cnt: 5; Type: USB - mini B; Vendor: Molex
J14 = EM,CONN,4P,EH,Devasys: DigiKey: 455-1627-ND; DigiReel: ---; Family: electro/mechanical; Index PN: 1005; Install: DNI; Lead Style: TH; MFG: JST; Part Specific: CONN HEADER EH SIDE 4POS 2.5MM; Type: connector
R8-R10 R19-R21 = PAS,R,large: DigiKey: YAG3111CT-ND; DigiReel: YAG3111DKR-ND; Family: passive; Lead Style: SMT; MFG: Yageo; Material: chip; P/D_NUM: RC0402FR-0730R1L; Part Number: RC0402FR-0730R1L; Part Specific: RES 30.1 OHM 1/16W 1% 0402 SMD; Power: 1/16W; TOLERANCE: 1%; Type: resistor; VPC: 1/16W; Vendor: Yageo
R47 = PAS,R,large: DigiKey: P0.0JCT-ND; DigiReel: P0.0JDKR-ND; Family: passive; Index PN: 687; Install: Y; Lead Style: SMT; MFG: Panasonic; Material: chip; P/D_NUM: ERJ-2GE0R00X; Part Number: ERJ-2GE0R00X; Part Specific: RES 0.0 OHM 1/16W 0402 SMD; Power: 1/16W; Type: resistor; VPC: 1/16W; Vendor: Panasonic
R81 = PAS,R,large: DigiKey: 311-100KLRCT-ND; DigiReel: 311-100KLRDKR-ND; Family: passive; Lead Style: SMT; MFG: Yageo; Material: chip; P/D_NUM: RC0402FR-07100KL; Part Number: RC0402FR-07100KL; Part Specific: RES SMD 100K OHM 1% 1/16W 0402; Power: 1/16W; TOLERANCE: 1%; Type: resistor; VENDOR: Yageo; VPC: 1/16W
R99-R102 = PAS,R,large: DigiKey: P0.0JCT-ND; DigiReel: P0.0JDKR-ND; Family: passive; Index PN: 687; Lead Style: SMT; MFG: Panasonic; Material: chip; P/D_NUM: ERJ-2GE0R00X; Part Number: ERJ-2GE0R00X; Part Specific: RES 0.0 OHM 1/16W 0402 SMD; Power: 1/16W; Type: resistor; VENDOR: Panasonic; VPC: 1/16W
TP3 TP9 TP10 TP19-TP27 TP29 = EM,TERM,TESTPOINT: DigiKey: ---; DigiReel: ---; Family: board feature; Index PN: 995; Install: DNI; MFG: -- NOT A PART --; Type: hole,plated; Vendor: -- NOT A PART --
U7 = LOG,XCVR,SN74AVC4T774PW,4_0: DigiKey: 296-24739-1-ND; DigiReel: 296-24739-6-ND; Part Specific: IC BUS TRANSCVR 4BIT DL 16TSSOP; Type: transceiver
U11 = TXS0102: DigiKey: 296-21931-1-ND; DigiReel: 296-21931-6-ND; Family: interface; Index PN: 877; Install: Y; Lead Style: SMT; MFG: Texas Instruments; P/D_NUM: TXS0102DCUR; Part Number: TXS0102DCUR; Part Specific: IC VOLT-LEVEL TRANSLATOR 8-US8; Type: driver; VENDOR: Texas Instruments
U12 = INF,USB2SERIAL,CY7C65215: DigiKey: CY7C65215-32LTXI-ND; DigiReel: ---; Family: interface; Index PN: 1217; Lead Style: SMT; MFG: Cypress; Part Specific: IC USB TO UART BRIDGE DUAL 32QFN; Type: usb; Vendor: Cypress
U25 = PAS,DIODE,TVS,TPD2E2U06DRL: DigiKey: 296-38361-1-ND; DigiReel: 296-38361-6-ND; Family: passive; Index PN: 1340; Lead Style: SMT; MFG: Texas Instruments; P/D_NUM: TPD2E2U06DRLR; Part Number: TPD2E2U06DRLR; Part Specific: TVS DIODE 5.5VWM 12.4VC 5SOT; Type: diode,tvs

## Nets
AVCC12: C13.2(N) C30.2(N) F1.2(N2) U22.22(AVCC12)
AVCC33: C32.1(P) C33.1(P) C34.1(P) C37.1(P) C40.1(P) F5.2(N2) U22.25(AVCC33) U22.30(AVCC33) U22.35(AVCC33) U22.40(APVCC33)
DGND: C3.2(N) C6.2(N) C7.2(N) C8.2(N) C9.2(N) C10.2(N) C11.2(N) C12.2(N) C13.1(P) C14.1(P) C15.1(P) C18.2(N) C19.2(N) C21.2(N) C22.2(N) C23.2(N) C24.2(N) C25.2(N) C26.2(N) C27.2(N) C28.2(N) C29.2(N) C30.1(P) C31.1(P) C32.2(N) C33.2(N) C34.2(N) C35.1(P) C36.1(P) C37.2(N) C38.1(P) C39.1(P) C40.2(N) C41.1(P) C42.2(N) C43.2(N) C52.2 C61.2(N) C66.2(N) C69.1(P) C70.1(P) C71.2(N) C72.1(P) C73.2(N) C75.2(N) C76.2(N) C77.2(N) C78.1(P) C79.2(N) C80.2(N) C81.2(N) C82.2(N) C83.2(N) C84.2(N) C85.2(N) C86.2(N) C88.2(N) C89.2(N) C93.2(N) C97.2(N) C98.2(N) C99.2(N) C100.2(N) C103.2(N) J3.1(SHIELD) J5.2 J6.5 J6.8 J6.11 J6.17 J6.20 J6.21 J6.22 J6.23 J9.61(G1) J9.62(G2) J9.63(G3) J9.64(G4) J12.1 J13.5(GND) J13.6(GND) J13.7(GND) J13.8(GND) J13.9(GND) J14.3 R3.2(N2) R42.2(N2) R57.1(N1) R58.1(N1) R78.1(N1) R79.2(N2) R81.1(N1) U2.1(IOVSS) U2.16(AVSS) U2.18(DVSS) U2.20(SPLVSS) U2.25(SPRVSS) U2.29(HPVSS) U2.33(PAD) U3.4(GND) U4.4(GND) U6.3(GND) U7.10(GND) U8.2(GND) U10.2(GND) U11.2(GND) U12.4(VSSD) U12.17(VSSD) U12.20(VSSD) U12.24(VSSA) U12.33(PAD) U13.2(GND) U14.2(GND) U16.4(GND) U17.1(A0) U17.2(A1) U17.3(A2) U17.4(GND) U18.3(GND) U19.3(GND) U20.2(GND) U21.2(GND) U22.77(EXPOSED_GND_PAD) U23.3(GND) U25.4(GND) U26.3(GND) U27.3(GND) U28.3(GND) U29.3(GND) VR1.1(A) ; also on sheet 8 9
P5V_VIN: C75.1(P) C76.1(P) C77.1(P) D4.1(A2) J9.55(P55) J9.56(P56) J9.57(P57) J9.58(P58) J9.59(P59) J9.60(P60) U2.21(SPLVDD) U2.24(SPRVDD) U3.1(VCC) U4.1(VCC) U10.5(IN) U16.1(VCC) ; also on sheet 8
PVCC12: C31.2(N) C72.2(N) F2.2(N2) U22.23(PVCC12)
PVCC33: C39.2(N) C41.2(N) F6.2(N2) U22.24(PVCC33)
VCCD: C61.1(P) U12.16(VCCD)
1DIR: R83.1(N1) U7.1(1DIR)
2DIR: R82.1(N1) U7.2(2DIR)
3DIR: R79.1(N1) U7.7(3DIR)
3DR: J9.31(P31) R74.2(N2)
3DR_T: R74.1(N1) U22.44(I2S1_3DR)
4DIR: R23.1(N1) U7.8(4DIR)
APVDD12: C36.2(N) C38.2(N) F4.2(N2) U22.37(APVDD12)
AUD_HPL: C2.1(P) U2.27(HPL)
AUD_HPR: C1.1(P) U2.30(HPR)
AUD_LEFT_OUT: C2.2(N) J3.2(LEFT)
AUD_P3P3V: C14.2(N) C15.2(N) C73.1(P) C78.2(N) C79.1(P) F3.2(N2) U2.17(AVDD) U2.28(HPVDD) VR1.3(E)
AUD_RIGHT_OUT: C1.2(N) J3.3(RIGHT)
AUD_SPLM: J8.4 U2.19(SPLM)
AUD_SPLP: J8.3 U2.22(SPLP)
AUD_SPRM: J8.2 U2.23(SPRM)
AUD_SPRP: J8.1 U2.26(SPRP)
CBUS_HPD: R59.1(N1) U22.21(CBUS/HPD)
CDSENSE: C71.1(P) J6.2 R58.2(N2) U22.19(CDSENSE)
CEC0: J6.13 U3.6(IO2)
DATEN_CMD: J9.17(P17) R64.1(N1)
DDCSCL0: R60.1(N1) U22.17(DDCSCL0)
DDCSDA0: R61.1(N1) U22.16(DDCSDA0)
DE_T: R64.2(N2) U22.8(DE)
EDID_WP0: J5.1 R52.1(N1) U17.7(WP)
EDIDO0_5V: C69.2(N) D4.3(K) R5.1(N1) R11.2(N2) R50.1(N1) R51.2(N2) R52.2(N2) U17.8(VCC)
ENVBUS#: Q1.1(GATE) R51.1(N1) U10.4(EN) U22.11(ENVBUS#)
EXT_I2CPWR: C66.1(P) F8.1(N1) J14.4
EXT_I2CPWR_F: C98.1(P) F8.2(N2) R47.1(N1) TP29.1(P1)
EXT_SCL: J14.2 R48.2(N2) U16.6(IO2)
EXT_SDA: J14.1 R49.2(N2) U16.3(IO1)
GPIO_0: U12.25(GPIO_0) U27.2(A)
GPIO_0_LED: D11.1(P1) R100.1(N1)
GPIO_0_LED_DRV: R100.2(N2) U27.4(Y)
GPIO_1: U12.26(GPIO_1) U26.2(A)
GPIO_1_LED: D10.1(P1) R99.1(N1)
GPIO_1_LED_DRV: R99.2(N2) U26.4(Y)
GPIO_2: TP25.1(P1) U12.27(SCB0_1/GPIO_2)
GPIO_5: R92.2(N2) TP26.1(P1) U12.30(SCB0_4/GPIO_5)
GPIO_6: R91.2(N2) TP10.1(P1) U12.31(GPIO_6)
GPIO_7: TP9.1(P1) U6.2(A) U12.32(GPIO_7)
GPIO_11: R21.1(N1) U12.6(SCB1_1/GPIO_11)
GPIO_12: R20.1(N1) U12.7(SCB1_2/GPIO_12)
GPIO_13: R19.1(N1) U12.8(SCB1_3/GPIO_13)
GPIO_14: TP3.1(P1) U12.9(SCB1_4/GPIO_14)
GPIO_16: TP20.1(P1) U12.13(GPIO_16)
GPIO_17: TP22.1(P1) U12.21(GPIO_17)
GPIO_18: TP23.1(P1) U12.22(GPIO_18)
HDMI_0_VCC5: C82.1(P) D4.2(A1) J6.18 R4.2(N2) U10.1(OUT)
HDMI_SCL: J6.15 Q1.3(DRAIN) R11.1(N1) U4.6(IO2)
HOST_IRQ: J9.35(P35) U12.10(SCB1_5/GPIO_15) U18.2(A) ; also on sheet 9
HOST_IRQ_LED: D1.1(P1) R65.1(N1)
HOST_IRQ_LED_DRV: R65.2(N2) U18.4(Y)
HSYNC_CS: J9.27(P27) R63.1(N1)
HSYNC_T: R63.2(N2) U22.9(HSYNC)
IIC0_SCL: J9.43(P43) R48.1(N1) TP24.1(P1) U2.10(SCL) U11.5(A1) U22.14(PCSCL) ; also on sheet 9
IIC0_SDA: J9.39(P39) R49.1(N1) TP27.1(P1) U2.9(SDA) U11.4(A2) U22.13(PCSDA) ; also on sheet 9
INTZ_CEC: R14.2(N2) U22.12(INT#_CEC)
IT6801_INTN: R14.1(N1) R15.1(N1) ; also on sheet 9
IT6801_RSTN: R16.1(N1) ; also on sheet 9
IT6801_RSTN_T: R16.2(N2) U2.31(/RESET)
LS_OUT: J9.52(P52) TP6.1(P1)
MICDET: J3.4(DETECT) J4.3
MSP430_ACK: R91.1(N1) U28.2(A) ; also on sheet 9
MSP430_ACK_LED: D8.1(P1) R101.1(N1)
MSP430_ACK_LED_DRV: R101.2(N2) U28.4(Y)
MSP430_REQ: R92.1(N1) U29.2(A) ; also on sheet 9
MSP430_REQ_LED: D9.1(P1) R102.1(N1)
MSP430_REQ_LED_DRV: R102.2(N2) U29.4(Y)
P1P2V: C6.1(P) C9.1(P) C10.1(P) C22.1(P) C24.1(P) C28.1(P) C29.1(P) C35.2(N) F1.1(N1) F2.1(N1) F4.1(N1) U22.7(IVDD12) U22.15(IVDD12) U22.36(DVDD12) U22.43(IVDD12) U22.48(IVDD12) U22.64(IVDD12) U22.71(IVDD12) ; also on sheet 8
P1P8V: C81.1(P) J9.54(P54) U2.3(DVDD) U8.5(Vcc) U13.5(Vcc) U14.5(Vcc) ; also on sheet 8
P3P3V_SB: C3.1(P) C7.1(P) C8.1(P) C12.1(P) C18.1(P) C19.1(P) C21.1(P) C23.1(P) C25.1(P) C26.1(P) C27.1(P) C42.1(P) C43.1(P) C80.1(P) C85.1(P) C86.1(P) C88.1(P) C89.1(P) C93.1(P) C97.1(P) C99.1(P) C103.1(P) D1.2(P2) D2.2(P2) D3.2(P2) D8.2(P2) D9.2(P2) D10.2(P2) D11.2(P2) F3.1(N1) F5.1(N1) F6.1(N1) J9.48(P48) J9.50(P50) R15.2(N2) R22.2(N2) R23.2(N2) R43.1(N1) R45.1(N1) R47.2(N2) R77.2(N2) R82.2(N2) R83.2(N2) U2.2(IOVDD) U6.5(PWR) U7.15(VCCB) U7.16(VCCA) U11.3(VCCA) U11.7(VCCB) U12.1(VDDD) U12.23(VDDD) U18.5(PWR) U19.5(PWR) U20.5(VCC) U21.5(VCC) U22.6(OVDD) U22.20(OVDD33) U22.50(OVDD) U22.55(OVDD) U22.63(OVDD) U22.70(OVDD) U22.76(OVDD) U23.5(PWR) U26.5(PWR) U27.5(PWR) U28.5(PWR) U29.5(PWR) ; also on sheet 8 9
PCADR: R78.2(N2) U22.49(PCADR)
PCLK: J9.19(P19) R7.1(N1)
PCLK_T: R7.2(N2) U22.75(PCLK)
PDATA0: J9.9(P9) RA1.16(I16)
PDATA1: J9.1(P1) RA1.15(I15)
PDATA2: J9.11(P11) RA1.14(I14)
PDATA3: J9.3(P3) RA1.13(I13)
PDATA4: J9.13(P13) RA1.12(I12)
PDATA5: J9.5(P5) RA1.11(I11)
PDATA6: J9.15(P15) RA1.10(I10)
PDATA7: J9.7(P7) RA1.9(I9)
PDATA8: J9.4(P4) RA2.16(I16)
PDATA9: J9.6(P6) RA2.15(I15)
PDATA10: J9.8(P8) RA2.14(I14)
PDATA11: J9.21(P21) RA2.13(I13)
PDATA12: J9.10(P10) RA2.12(I12)
PDATA13: J9.25(P25) RA2.11(I11)
PDATA14: J9.12(P12) RA2.10(I10)
PDATA15: J9.29(P29) RA2.9(I9)
PDATA16: J9.14(P14) RA3.16(I16)
PDATA17: J9.33(P33) RA3.15(I15)
PDATA18: J9.16(P16) RA3.14(I14)
PDATA19: J9.37(P37) RA3.13(I13)
PDATA20: J9.18(P18) RA3.12(I12)
PDATA21: J9.41(P41) RA3.11(I11)
PDATA22: J9.20(P20) RA3.10(I10)
PDATA23: J9.45(P45) RA3.9(I9)
PDATA_T0: RA1.1(I1) U22.5(QE4)
PDATA_T1: RA1.2(I2) U22.4(QE5)
PDATA_T2: RA1.3(I3) U22.3(QE6)
PDATA_T3: RA1.4(I4) U22.2(QE7)
PDATA_T4: RA1.5(I5) U22.1(QE8)
PDATA_T5: RA1.6(I6) U22.74(QE9)
PDATA_T6: RA1.7(I7) U22.73(QE10)
PDATA_T7: RA1.8(I8) U22.72(QE11)
PDATA_T8: RA2.1(I1) U22.69(QE16)
PDATA_T9: RA2.2(I2) U22.68(QE17)
PDATA_T10: RA2.3(I3) U22.67(QE18)
PDATA_T11: RA2.4(I4) U22.66(QE19)
PDATA_T12: RA2.5(I5) U22.65(QE20)
PDATA_T13: RA2.6(I6) U22.62(QE21)
PDATA_T14: RA2.7(I7) U22.61(QE22)
PDATA_T15: RA2.8(I8) U22.60(QE23)
PDATA_T16: RA3.1(I1) U22.59(QE28)
PDATA_T17: RA3.2(I2) U22.58(QE29)
PDATA_T18: RA3.3(I3) U22.57(QE30)
PDATA_T19: RA3.4(I4) U22.56(QE31)
PDATA_T20: RA3.5(I5) U22.54(QE32)
PDATA_T21: RA3.6(I6) U22.53(QE33)
PDATA_T22: RA3.7(I7) U22.52(QE34)
PDATA_T23: RA3.8(I8) U22.51(QE35)
PDM_CVS_TE: J9.23(P23) TP1.1(P1)
PROJ_ON: J9.36(P36) U23.2(A) ; also on sheet 9
PROJ_ON_LED: D3.1(P1) R70.1(N1)
PROJ_ON_LED_DRV: R70.2(N2) U23.4(Y)
PWR_TP_SEN: J9.38(P38) J9.40(P40) J12.8 R80.1(N1) R86.1(N1) R87.1(N1) R88.1(N1) R89.1(N1) R90.1(N1) ; also on sheet 8
R0PWR5V: C11.1(P) R3.1(N1) R4.1(N1) U22.18(R0PWR5V)
R0X0M: J6.9 U20.1(D1+) U22.28(P0_RX0N)
R0X0P: J6.7 U20.6(D1-) U22.29(P0_RX0P)
R0X1M: J6.6 U21.4(D2-) U22.31(P0_RX1N)
R0X1P: J6.4 U21.3(D2+) U22.32(P0_RX1P)
R0X2M: J6.3 U21.1(D1+) U22.33(P0_RX2N)
R0X2P: J6.1 U21.6(D1-) U22.34(P0_RX2P)
R0XCM: J6.12 U20.4(D2-) U22.26(P0_RXCN)
R0XCP: J6.10 U20.3(D2+) U22.27(P0_RXCP)
RESETZ: J9.53(P53) U19.2(A)
RESETZ_LED: D2.1(P1) R66.1(N1)
RESETZ_LED_DRV: R66.2(N2) U19.4(Y)
RX_DDCSCL0: Q1.2(SOURCE) R5.2(N2) R60.2(N2) U17.6(SCL)
RX_DDCSDA0: J6.16 R50.2(N2) R61.2(N2) U4.3(IO1) U17.5(SDA)
RX_HPD0: J6.19 R57.2(N2) R59.2(N2) U3.3(IO1)
RX_I2S0: R73.2(N2) U2.5(DIN)
RX_I2S0_T: R73.1(N1) U22.42(I2S0)
RX_MCLK: R72.2(N2) U2.8(MCLK)
RX_MCLK_T: R72.1(N1) U22.41(MUTE_MCLK)
RX_SCK: R76.2(N2) U2.7(BCLK)
RX_SCK_T: R76.1(N1) U22.46(SCK_MCLK)
RX_WS: R75.2(N2) U2.6(WCLK)
RX_WS_T: R75.1(N1) U22.45(WS_SPDIF)
SPI0_CLK: J9.46(P46) R8.1(N1)
SPI0_CSZ0: J9.51(P51) R10.1(N1)
SPI0_MISO: J9.47(P47) U7.12(B3)
SPI0_MOSI: J9.49(P49) R9.1(N1)
SUSPEND: TP19.1(P1) U12.11(SUSPEND)
SW_ONOFF: U6.4(Y) ; also on sheet 9
SYSRSTN: C52.1 R77.1(N1) U22.47(SYSRSTN)
TSTPT_0: J9.22(P22) U8.1(1A)
TSTPT_0_BF: J12.7 R80.2(N2) U8.6(1Y)
TSTPT_1: J9.24(P24) U8.3(2A)
TSTPT_1_BF: J12.6 R86.2(N2) U8.4(2Y)
TSTPT_2: J9.26(P26) U13.1(1A)
TSTPT_2_BF: J12.5 R87.2(N2) U13.6(1Y)
TSTPT_3: J9.28(P28) U13.3(2A)
TSTPT_3_BF: J12.4 R88.2(N2) U13.4(2Y)
TSTPT_6: J9.30(P30) U14.1(1A)
TSTPT_6_BF: J12.3 R89.2(N2) U14.6(1Y)
TSTPT_7: J9.32(P32) U14.3(2A)
TSTPT_7_BF: J12.2 R90.2(N2) U14.4(2Y)
USB_IIC0_OE: R42.1(N1) U11.6(OE) U12.3(SCB0_5/GPIO_9)
USB_IIC0_SCL: R43.2(N2) U11.8(B1) U12.28(SCB0_2/GPIO_3)
USB_IIC0_SDA: R45.2(N2) U11.1(B2) U12.29(SCB0_3/GPIO_4)
USB_SPI_CLK: R19.2(N2) U7.3(A1)
USB_SPI_CLK_T: R8.2(N2) U7.14(B1)
USB_SPI_CSZ0: R20.2(N2) U7.6(A4)
USB_SPI_MISO: R81.2(N2) U7.5(A3) U12.5(SCB1_0/GPIO_10)
USB_SPI_MOSI: R21.2(N2) U7.4(A2)
USB_SPI_MOSI_T: R9.2(N2) U7.13(B2)
USB_SPI_OEz: R22.1(N1) U7.9(~{OE}) U12.2(SCB0_0/GPIO_8)
USB_SPICSZ0_T: R10.2(N2) U7.11(B4)
USB_VBUS: C100.1(P) J13.1(VUSB) U12.19(VBUS)
USBDM: J13.2(D-) U12.15(USBDM) U25.3(IO1)
USBDP: J13.3(D+) U12.14(USBDP) U25.5(IO2)
VOL_MICDET: J4.2 U2.11(VOL/MICDET)
VOL_POT: C70.2(N) J4.1 VR1.2(WIPER)
VSYNC_T: R62.2(N2) U22.10(VSYNC)
VSYNC_WE: J9.2(P2) R62.1(N1)
WAKEUP: TP21.1(P1) U12.12(WAKEUP)
XTALIN: C84.1(P) R68.1(N1) U22.39(XTALIN) X1.3(N)
XTALOUT: C83.1(P) R68.2(N2) U22.38(XTALOUT) X1.1(P)

Not connected (* = marked no-connect by the designer): J3 5(LSHUNT)* 6(RSHUNT)*; J6 14*; J9 34(P34) 42(P42) 44(P44); J13 4(ID)*; U2 4(NC2)* 12(MICBIAS)* 13(AIN1)* 14(AIN2)* 15(NC1)* 32(GPIO1)*; U3 2(NC2)* 5(NC5)*; U4 2(NC2)* 5(NC5)*; U10 3(~{FLT})*; U12 18(nXRES)*; U16 2(NC2)* 5(NC5)*; U25 1(NC1)* 2(NC2)*

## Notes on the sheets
sheet 2
- Audio outputs have some
  optional configurations,
  please refer to datasheet
  for details.
- PS: Please contact ITE
   for finalizing the I2C
   control circuits.
sheet 4
- Revisions
- Rev. E.0 : Development version
                   Changed Input power to 19V
                   Removed 3.3V regulator and added 3.3V_SB regulator
                   Changed ITE OVDD voltage to 3.3V
  Rev. E.1:  Changed R56 to install and R55 to DNI - The power for the MSP430 will be supplied by the input power not the debugger
                   Changed J12 and J14 to DNI
                   Changed Title to accommodate new part number
  Rev.   A :  Removed ESD number, General clean-up, Changed Revision to A
sheet 5
- PDATA[0:7] = B[0:7]
  PDATA[8:15] = G[0:7]
  PDATA[16:23] = R[0:7]
sheet 7
- DEVASYS CONNECTOR
- Need EX_I2CPWR wire
  (3.3V) from the Devasys Box
- SCB0 configured as I2C Master (Mode 5)
  SCB1 configured as SPI Master (Mode 3)
